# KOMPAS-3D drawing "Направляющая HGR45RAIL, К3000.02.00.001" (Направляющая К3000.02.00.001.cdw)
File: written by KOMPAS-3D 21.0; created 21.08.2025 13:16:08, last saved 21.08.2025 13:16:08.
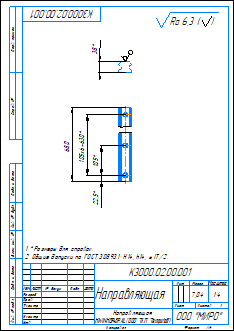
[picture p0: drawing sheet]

Sheet 1: A4, portrait

Document properties: Автор: admin; Полное имя файла: C:\Users\ShavarinML\Desktop\Стапель\2D\Направляющая К3000.02.00.001.cdw; Знак неуказанной шероховатости: 4; Параметр неуказанной шероховатости: Ra 6,3; Масса: 7.044252

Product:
- Part/product: Направляющая HGR45RAIL  | designation К3000.02.00.001
    Масса: 7.044252
  - Body: Тело 1
      Масса: 7.04425

Title block, sheet 1: Наименование: Направляющая; designation: К3000.02.00.001; Материал: Направляющая / HIWIN-HGR45RAIL ("ООО" "ТКП" "Техпривод"); Масса: 7,04; Количество листов документа: 1; organisation: ООО "МИРО"; Форматы листов документа: A4

Views: Спереди 1, Спереди, Проекционный вид 2
Referenced files in C:\Users\ShavarinML\Desktop\Стапель\Задняя бабака\Направляющие\Профильные направляющие HIWIN\: HGR45RAIL.m3d
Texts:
  Ra 6,3
  Ra 6,3 ( )
  Направляющая HGR45RAIL
  К3000.02.00.001 Направляющая HGR45RAIL
Dimensions and other numbers on the sheet: 38; 22,5; 105; 105х6=630; 680; 1:4; 1; 7,04

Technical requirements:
  *Размеры для справок.
  Общие допуски по ГОСТ 30893.1: H14, h14,   IT/2.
